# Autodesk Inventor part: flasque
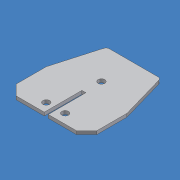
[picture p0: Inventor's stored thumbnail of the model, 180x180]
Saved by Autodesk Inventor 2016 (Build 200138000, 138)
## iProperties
Shininess: 64.0
Length Units: 11269
Angle Units: 11279
Time Units: 11290
Mass Units: 11283
Length Display Precision: 3
Angle Display Precision: 2
Compacted: True
Part Number: flasque
Document SubType Name: Modeling
Created: 2003-07
Material: Générique
Designer: trameau
Density: 1 g/cm^3
Appearance: Par défaut
Density: 0.0
Volumn: 0.0
Area: 0.0
PropertySet Name: Model Information
Control State: 0
Master: False
Checked Out: False
Author: trameau
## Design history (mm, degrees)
sketch "Esquisse1"
  geometry: L1 (22.213, 103.7)-(-14.016, 103.7); L2 (-18.823, 100.074)-(-37.787, 33.7); L3 (-37.787, 33.7)-(-37.787, -11.3); L4 (-22.787, -26.3)-(19.213, -26.3); L5 (19.213, -26.3)-(19.213, 29.7); L6 (19.213, 29.7)-(22.213, 29.7); L7 (22.213, 29.7)-(22.213, 103.7); L8 (-22.787, -26.3)-(-37.787, -11.3); A1 r 5 centre (-14.016, 98.7) between (-14.016, 103.7) and (-18.823, 100.074); 2 further points
  constraints: 16 end point, 4 parallel, 4 point on line, 2 point on circle, 2 tangent, 1 centre point, 1 horizontal, 1 perpendicular
  dimensions: "d0" = 60 distance between parallel lines of L7 L3; "d1" = 40 distance of L1.start point (-17.787, 103.7); "d2" = 57 distance between parallel lines of L5 L3; "d3" = 130 distance between parallel lines of L1 L4; "d4" = 56 distance of L4.end L5.end; "d5" = 60 distance of L2.end point (-37.787, -26.3); "d6" = 15 distance of L4.start point (-37.787, -26.3); "d7" = 15 distance of L3.end point (-37.787, -26.3) (= d6); "d8" = 5 radius of A1
extrude "Extrusion1" new body sketch "Esquisse1" distance "d9" = 5; taper "d10" = 0 deg
mirror "Symétrie1"
sketch "Esquisse2"
  geometry: L1 (58.441, 103.7)-(-14.016, 103.7) reference; L2 (19.213, -26.3)-(-22.787, -26.3) reference; L3 (19.213, 29.7)-(19.213, -26.3) reference; L4 (25.213, -26.3)-(67.213, -26.3) reference; 3 further points
  dimensions: "d11" = 48 distance from line of L1 point (22.213, 55.7); "d12" = 14 distance from line of L2 point (8.213, -12.3); "d13" = 14 distance from line of L4 point (36.213, -12.3) (= d12); "d14" = 28 distance of point (8.213, -12.3) point (36.213, -12.3); "d15" = 11 distance from line of L3 point (8.213, -12.3)
hole "Perçage1" sketch "Esquisse2" at (8.213, -12.3), (36.213, -12.3), (22.213, 55.7) diameter "d20" = 10; stored, may be unused: countersink angle "d24" = 82 deg, drill point angle "d26" = 118 deg; dims "d21" = 6, "d22" = 4, "d23" = 2, "d25" = 8
node "Solide1"
node "Corps solides"
node "Corps surfaciques"
